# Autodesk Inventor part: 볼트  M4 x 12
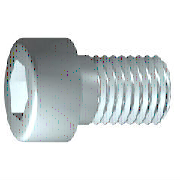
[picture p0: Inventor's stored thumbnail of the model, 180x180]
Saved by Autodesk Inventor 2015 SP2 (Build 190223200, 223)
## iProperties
IsCustomPart: 0
Created: 2015-12
Part Number: 볼트  M4 x 12
Material: 일반
Description: 6각머리 태핑 나사
Document SubType Name: Modeling
Standard: KS B 1003
Designer: mdu
Standards Organization: KS
Language: ko-KR
Size Designation: M 4 x 12
Categories: <MemberInstance><Categories><Category DisplayName="조임쇠" InternalName="e4da775c-781d-43d5-af7c-5136215cf5a6" Mnemonic="FSTN"><Category DisplayName="볼트" InternalN
Density: 1 g/cm^3
Mass: 0.284306 g
Surface Area: 3.30853 cm^2
Volume: 0.284306 cm^3
Appearance: 기본값
Author: mdu
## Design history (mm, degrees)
sketch "스케치1"
  geometry: L1 (-1, 0)-(12, 0); L2 (12, 0)-(12, 2); L3 (12, 2)-(1.75, 2); L4 (1.75, 2)-(1.32, 2); L5 (1.32, 2)-(0, 2); L6 (0, 2)-(0, 3.5); L7 (0, 3.5)-(-4, 3.5); L8 (-4, 3.5)-(-4, 1.732); L9 (-4, 1.732)-(-2, 1.732); L10 (-2, 1.732)-(-1, 0); L11 (-7.2, 0)-(15.2, 0) reference; L12 (0, -0.7)-(0, 4.2) reference; L13 (1.75, 2)-(0, 2)
  constraints: 22 end point, 6 parallel, 2 collinear, 2 perpendicular, 1 horizontal, 1 point on line
  dimensions: "d1" = 10.25 distance from line of L3.end L2 (= GEL); "d2" = 0.42952 distance of L4.end L3.end (computed from GAL); "d3" = 4 distance between parallel lines of L8 L6 (= KOH); "d4" = 2 distance of L8.end L9.end (= INTI); "d5" = 60 deg angle of L10 L1; "d6" = 4 diameter of L3 L1 (= GD); "d7" = 4 diameter of L5 L1 (= BDM); "d8" = 3.4641 diameter of L9 L1 (= 1.1547 x SW); "d9" = 7 diameter of L7 L1 (= KOD); "d26" = 12 distance between parallel lines of L12 L2 (= NLG)
revolve "본체" sketch "스케치1" stored, may be unused: angle "d10" = 90 deg
sketch "스케치2"
  geometry: L1 (0, -4.9)-(0, 4.9) reference; L2 (-4.9, 0)-(4.9, 0) reference; L3 (1.732, 0)-(0.866, -1.5); L4 (0.866, -1.5)-(-0.866, -1.5); L5 (-0.866, -1.5)-(-1.732, 0); L6 (-1.732, 0)-(-0.866, 1.5); L7 (-0.866, 1.5)-(0.866, 1.5); L8 (0.866, 1.5)-(1.732, 0); 2 further points
  constraints: 12 end point, 1 coincident, 1 horizontal alignment, 1 point on line, 12 other
extrude "슬롯" join sketch "스케치2" stored distance "d11" = 10; taper "d12" = 0 deg
workplane "Work Plane1"
fillet "Fillet2" dims "d30" = 0.1 (= R)
body "Solid1"
fillet "모깎기1" dims "d17" = 0.4 (= RR)
feature "스레드" dims "d13" = 10.25 (= GEL), "d14" = 0
chamfer "모따기1" distance "d15" = 0.42941 (= -0.5 x SPD + 0.5 x GD); stored, may be unused: second distance "d16" = 0.42941 (= GUL), angle "d27" = 45 deg
other parameters: "GD" = 4 (= NND) [user parameter; used in 2 equation terms], "NLG" = 12 [user parameter; used in 1 equation term], "GEL" = 10.25 [user parameter; used in 2 equation terms], "KOD" = 7 [user parameter; used in 1 equation term], "KOH" = 4 [user parameter; used in 1 equation term], "INTI" = 2 [user parameter; used in 1 equation term], "GAL" = 0.42941 (= 0.61345 x PTC) [user parameter; used in 1 equation term], "GUL" = 0.42941 (= 0.61345 x PTC) [user parameter; used in 1 equation term], "BDM" = 4 (= NND) [user parameter; used in 1 equation term], "SW" = 3 [user parameter; used in 2 equation terms], "RR" = 0.4 [user parameter; used in 1 equation term], "SPD" = 3.14117 (= NND - 1.2269 x PTC) [user parameter; used in 1 equation term], "d19" = 0, "d28" = 0, "d29" = 0, "R" = 0.1 [user parameter; used in 1 equation term], "PHH" = 0.2 [user parameter], "GD1" = 3.14117 (= THREADDIA - 1.2269 x PTC) [user parameter], "THREADDIA" = 4 [user parameter; used in 1 equation term], "FAWI" = 45 deg [user parameter], "TPU" = 14.28571 (computed from PTC) [user parameter], "PTC" = 0.7 [user parameter; used in 5 equation terms], "NND" = 4 [user parameter; used in 3 equation terms], "TOA" = 30 deg [user parameter], "E0" = 3.465 (= 1.155 x SW) [user parameter]
